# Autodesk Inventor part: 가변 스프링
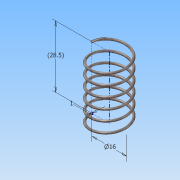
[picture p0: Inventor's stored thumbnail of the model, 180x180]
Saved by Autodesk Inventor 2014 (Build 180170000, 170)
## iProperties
Created: 2016-05
Part Number: 가변 스프링
Material: 스테인레스 스틸
Document SubType Name: Modeling
Designer: 703-04
Mass: 1.89959 g
Surface Area: 9.48061 cm^2
Volume: 0.235098 cm^3
Density: 8.08 g/cm^3
Appearance: 반연마
Author: 703-04
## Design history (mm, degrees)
sketch "스케치2"
  geometry: L1 (0, 0)-(8, 0); L2 (8, 0)-(8, 28.5); L3 (8, 28.5)-(0, 28.5); L4 (0, 28.5)-(0, 0); C1 r 0.5 at (8, 0)
  constraints: 8 end point, 2 parallel, 1 centre point, 1 coincident, 1 horizontal, 1 perpendicular
  dimensions: "d0" = 16 diameter of L2 L4; "d1" = 28.49959 distance between parallel lines of L3 L1 (derived); "d2" = 1 diameter of C1
feature "코일1" pitch "d3" = 10; turns "d5" = 6; dims "d4" = 28.49959 (= d1), "d6" = 0, angle "d7" = 90 deg, angle "d8" = 90 deg, "d9" = 0, "d10" = 0
sketch "스케치3"
  geometry: L1 (-8.5, 0)-(-7.5, 0) reference; 1 further point
  constraints: 1 horizontal alignment
extrude "돌출1" cut sketch "스케치3" stored distance "d11" = 10; taper "d12" = 0 deg
node "작업 평면1"
sketch "스케치4"
  geometry: L1 (8.5, 0)-(7.5, 0) reference; 1 further point
  constraints: 1 horizontal alignment
extrude "돌출2" cut sketch "스케치4" stored distance "d13" = 10; taper "d14" = 0 deg
node "솔리드1"
node "절단 모서리 투영1"
node "절단 모서리 투영2"
